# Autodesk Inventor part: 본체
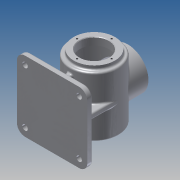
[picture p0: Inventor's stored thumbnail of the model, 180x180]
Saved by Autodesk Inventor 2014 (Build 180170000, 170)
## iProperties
Created: 2015-07
Part Number: 본체
Material: 알루미늄 6061
Document SubType Name: Modeling
Designer: SDA21
Density: 2.71 g/cm^3
Appearance: 알루미늄 - 평지
Mass: 1277.62 g
Surface Area: 1267.61 cm^2
Volume: 471.447 cm^3
Author: SDA21
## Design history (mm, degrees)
sketch "스케치2"
  geometry: L1 (65, -65)-(-65, -65); L2 (-65, -65)-(-65, 65); L3 (-65, 65)-(65, 65); L4 (65, 65)-(65, -65); 3 further points
  constraints: 8 end point, 2 midpoint, 2 parallel, 2 perpendicular, 1 horizontal, 1 horizontal alignment, 1 vertical alignment
  dimensions: "d0" = 130 distance of L3.end L1.start
extrude "돌출1" new body sketch "스케치2" distance "d1" = 10; taper "d2" = 0 deg
node "작업 평면1"
sketch "스케치3"
  geometry: L1 (130, 0)-(0, 0) reference; C1 r 45 at (65, 78); 2 further points
  constraints: 1 centre point, 1 midpoint, 1 vertical alignment
  dimensions: "d4" = 90 diameter of C1; "d5" = 78 distance from line of C1.centre L1
extrude "돌출2" join sketch "스케치3" distance "d6" = 110; taper "d7" = 0 deg
sketch "스케치4"
  geometry: C1 r 45 at (0, 0) reference; C2 r 38 at (0, 0); 1 further point
  constraints: 1 centre point, 1 coincident
  dimensions: "d8" = 76 diameter of C2
extrude "돌출3" join sketch "스케치4" distance "d9" = 7; taper "d10" = 0 deg
node "작업 평면2"
sketch "스케치5"
  geometry: C1 r 38 at (0, 0); 1 further point
  constraints: 1 centre point, 1 coincident
  dimensions: "d12" = 76 diameter of C1
extrude "돌출4" join sketch "스케치5" stored distance "d13" = 7; taper "d14" = 0 deg
sketch "스케치7"
  geometry: L1 (-45, 5)-(45, 5); L2 (45, 5)-(45, -5); L3 (45, -5)-(-45, -5); L4 (-45, -5)-(-45, 5); L5 (-5, 45)-(5, 45); L6 (5, 45)-(5, -45); L7 (5, -45)-(-5, -45); L8 (-5, -45)-(-5, 45); 5 further points
  constraints: 16 end point, 4 midpoint, 4 parallel, 2 horizontal, 2 horizontal alignment, 2 perpendicular, 2 vertical alignment
  dimensions: "d15" = 10 distance of L3.end L1.start; "d16" = 90 distance of L1.start L1.end; "d17" = 10 distance of L5.start L5.end; "d18" = 90 distance of L5.end L6.end
extrude "돌출5" join sketch "스케치7" stored distance "d19" = 7; taper "d20" = 0 deg
sketch "스케치8"
  geometry: C1 r 38 at (0, 0) reference; C2 r 27 at (0, 0); 1 further point
  constraints: 1 centre point, 1 coincident
  dimensions: "d21" = 54 diameter of C2
extrude "돌출6" cut sketch "스케치8" distance "d22" = 14; taper "d23" = 0 deg
sketch "스케치9"
  geometry: C1 r 27 at (0, 0) reference; C2 r 40 at (0, 0); 1 further point
  constraints: 1 centre point, 1 coincident
  dimensions: "d24" = 80 diameter of C2
extrude "돌출7" cut sketch "스케치9" distance "d25" = 96; taper "d26" = 0 deg
sketch "스케치10"
  geometry: C1 r 38 at (0, 0) reference; C2 r 27 at (0, 0)
  constraints: 1 centre point, 1 coincident
  dimensions: "d27" = 54 diameter of C2
extrude "돌출8" cut sketch "스케치10" stored distance "d28" = 96; taper "d29" = 0 deg
sketch "스케치11" dims "d30" = 64
  geometry: C1 r 27 at (0, 0) reference; C2 r 38 at (0, 0) reference; 2 further points
  constraints: 2 vertical alignment, 1 coincident, 2 other
hole "구멍1" sketch "스케치11" at (0, 32) diameter "d31" = 3.242; stored, may be unused: countersink angle "d35" = 90 deg, drill point angle "d37" = 118 deg; dims "d32" = 8, "d33" = 4, "d34" = 2, "d36" = 10
sketch "스케치12" dims "d41" = 64
  geometry: C1 r 38 at (0, 0) reference; 3 further points
  constraints: 2 vertical alignment, 1 coincident, 2 other
hole "구멍2" sketch "스케치12" at (0, 32) diameter "d42" = 3.242; stored, may be unused: countersink angle "d46" = 90 deg, drill point angle "d48" = 118 deg; dims "d43" = 8, "d44" = 4, "d45" = 2, "d47" = 10
sketch "스케치13"
  geometry: C1 r 45 at (0, 0) reference; 2 further points
  constraints: 2 coincident, 1 other
feature "엠보싱1" sketch "스케치13" dims "d0" = 130, "d52" = 0.5, "d53" = 0
fillet "모깎기1" dims "d54" = 15
sketch "스케치15"
  geometry: C1 r 7.5 at (-50, 50); C2 r 7.5 at (50, 50); C3 r 7.5 at (-50, -50); C4 r 7.5 at (50, -50); A1 r 15 centre (-50, 50) between (-50, 65) and (-65, 50) reference; A2 r 15 centre (-50, -50) between (-65, -50) and (-50, -65) reference; A3 r 15 centre (50, -50) between (50, -65) and (65, -50) reference; A4 r 15 centre (50, 50) between (65, 50) and (50, 65) reference; 1 further point
  constraints: 4 centre point, 4 coincident
  dimensions: "d55" = 15 diameter of C1; "d56" = 15 diameter of C2; "d57" = 15 diameter of C3; "d58" = 15 diameter of C4
extrude "돌출9" join sketch "스케치15" distance "d59" = 3; taper "d60" = 0 deg
sketch "스케치16"
  geometry: C1 r 5 at (-50, 50); C2 r 5 at (50, 50); C3 r 5 at (-50, -50); C4 r 5 at (50, -50); A1 r 15 centre (-50, -50) between (-65, -50) and (-50, -65) reference; A2 r 15 centre (50, -50) between (50, -65) and (65, -50) reference; A3 r 15 centre (50, 50) between (65, 50) and (50, 65) reference; A4 r 15 centre (-50, 50) between (-50, 65) and (-65, 50) reference; 1 further point
  constraints: 4 centre point, 4 coincident
  dimensions: "d61" = 10 diameter of C1; "d62" = 10 diameter of C2; "d63" = 10 diameter of C3; "d64" = 10 diameter of C4
extrude "돌출10" cut sketch "스케치16" stored distance "d65" = 3; taper "d66" = 0 deg
chamfer "모따기1" distance "d67" = 1; stored, may be unused: second distance "d68" = 2, angle "d69" = 45 deg
chamfer "모따기2" distance "d70" = 1; stored, may be unused: second distance "d71" = 2, angle "d72" = 45 deg
fillet "모깎기2" dims "d73" = 3
fillet "모깎기3" dims "d74" = 3
fillet "모깎기4" dims "d75" = 3
fillet "모깎기5" dims "d76" = 3
node "솔리드1"
pattern_circular "원형 패턴1" dims angle "d39" = 360 deg
pattern_circular "원형 패턴2" dims angle "d50" = 360 deg
